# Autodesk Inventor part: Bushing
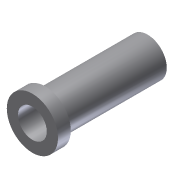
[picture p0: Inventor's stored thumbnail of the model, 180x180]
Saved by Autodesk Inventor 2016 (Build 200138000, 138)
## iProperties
Shininess: 77.0
Length Units: 11269
Angle Units: 11279
Time Units: 11290
Mass Units: 11283
Length Display Precision: 3
Angle Display Precision: 2
Created: 2002-02
Part Number: Bushing
Document SubType Name: Modeling
Designer: ***
Density: 1 g/cm^3
Material: Generic
Appearance: Default
Density: 0.0
Volumn: 0.0
Area: 0.0
PropertySet Name: Model Information
Control State: 0
Master: False
Checked Out: False
Author: ***
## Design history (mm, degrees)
sketch "Sketch1"
  geometry: L1 (6.25, 50.44)-(6.25, 5.44); L2 (6.25, 5.44)-(10.625, 5.44); L3 (10.625, 5.44)-(10.625, 10.44); L4 (10.625, 10.44)-(8.125, 10.44); L5 (8.125, 10.44)-(8.125, 50.44); L6 (8.125, 50.44)-(6.25, 50.44); L7 (0.625, 34.884)-(0.625, 0)
  constraints: 14 end point, 4 parallel, 2 perpendicular, 1 vertical
  dimensions: "d0" = 20 diameter of L3 L7; "d1" = 11.25 diameter of L1 L7; "d2" = 15 diameter of L5 L7; "d4" = 5 distance of L2.end L3.end; "d5" = 45 distance of L1.start L1.end
revolve "Revolution1" sketch "Sketch1" stored, may be unused: angle "d3" = 90 deg
body "Solid1"
